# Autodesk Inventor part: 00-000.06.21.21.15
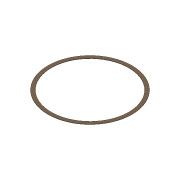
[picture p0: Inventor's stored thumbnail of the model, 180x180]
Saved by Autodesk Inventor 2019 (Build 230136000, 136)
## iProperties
Created: 2019-01
Part Number: 00-000.06.21.21.15
Material: MDF Medium Density Fiberboard
Document SubType Name: Modeling
Designer: m.vorobev
Density: 0.8 g/cm^3
Appearance: Cardboard - Corrugated
Author: m.vorobev
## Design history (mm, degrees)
sketch "Sketch1"
  geometry: L1 (115, 1)-(125, 1); L2 (125, 1)-(125, 0); L3 (125, 0)-(115, 0); L4 (115, 0)-(115, 1); L5 (0, 0)-(29.756, 0); L6 (29.756, 0)-(29.756, 30.712); L7 (29.756, 30.712)-(0, 30.712); L8 (0, 30.712)-(0, 0)
  constraints: 16 end point, 4 parallel, 2 horizontal, 2 perpendicular
  dimensions: "d0" = 250 diameter of L2 L8; "d1" = 230 diameter of L3.end L8; "d2" = 1 distance of L1.end L2.end
revolve "Revolution1" sketch "Sketch1" stored, may be unused: angle "d3" = 90 deg
body "Solid1"
